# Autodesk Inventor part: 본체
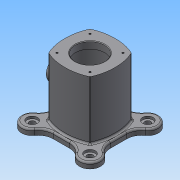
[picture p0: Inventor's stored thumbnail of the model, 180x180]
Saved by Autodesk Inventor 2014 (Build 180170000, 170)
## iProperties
Created: 2016-05
Part Number: 본체
Material: 일반
Document SubType Name: Modeling
Designer: NET
Density: 1 g/cm^3
Appearance: 기본값
Author: NET
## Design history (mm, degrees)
sketch "스케치5"
  geometry: L1 (0, 43)-(0, -43); L2 (-43, 0)-(43, 0); L3 (0, 0)-(35.355, 35.355); L4 (0, 0)-(-35.355, 35.355); L5 (0, 0)-(-35.355, -35.355); L6 (0, 0)-(35.355, -35.355); 4 further points; 4 other entities
  constraints: 12 end point, 2 coincident, 2 horizontal, 2 horizontal alignment, 2 midpoint, 2 vertical alignment, 18 other
  dimensions: "d44" = 50 distance of L3.end L3.start; "d46" = 50 distance of L4.end L3.start; "d47" = 50 distance of L5.end L3.start; "d48" = 45 deg angle of L2 L3; "d49" = 45 deg angle of L1 L4; "d50" = 45 deg angle of L1 L5; "d51" = 50 distance of L6.end L3.start; "d52" = 45 deg angle of L2 L6; "d53" = 86 distance of L1.end L1.start; "d54" = 86 distance of L2.start L2.end
extrude "돌출3" new body sketch "스케치5" distance "d55" = 110; taper "d56" = 0 deg
fillet "모깎기3" dims "d57" = 3
sketch "스케치6"
  geometry: L1 (110, -34.353)-(110, 34.353) reference; L2 (0, -34.353)-(0, 34.353) reference; L3 (110, 0)-(0, 0); L4 (110, -25)-(98, -25); L5 (98, -25)-(98, 0); L6 (98, -35)-(12, -35); L7 (12, -35)-(12, 0); L8 (0, -25)-(12, -25); L9 (12, -25)-(12, 0); L10 (98, -35)-(98, -25)
  constraints: 16 end point, 6 perpendicular, 5 point on line, 2 parallel, 1 midpoint
  dimensions: "d58" = 70 diameter of L6 L3; "d59" = 50 diameter of L4 L3; "d60" = 50 diameter of L8 L3; "d61" = 12 distance between parallel lines of L1 L5; "d62" = 12 distance between parallel lines of L2 L7
revolve "회전1" sketch "스케치6" stored, may be unused: angle "d63" = 90 deg
sketch "스케치7"
  geometry: L1 (-49, 49)-(49, 49); L2 (49, 49)-(49, -49); L3 (49, -49)-(-49, -49); L4 (-49, -49)-(-49, 49); L5 (0, 0)-(-49.497, -49.497); L6 (0, 0)-(0, -70); A1 r 18 centre (-49.497, -49.497) between (-34.706, -59.754) and (-59.754, -34.706); A2 r 25 centre (-14.162, -74) between (-14.162, -49) and (-34.706, -59.754); A3 r 25 centre (-74, -14.162) between (-59.754, -34.706) and (-49, -14.162); 3 further points
  constraints: 12 end point, 6 point on circle, 4 tangent, 3 centre point, 3 parallel, 2 coincident, 2 midpoint, 2 point on line, 1 horizontal, 1 horizontal alignment, 1 perpendicular, 1 vertical alignment
  dimensions: "d64" = 98 distance of L1.start L1.end; "d65" = 98 distance of L3.end L1.start; "d67" = 45 deg angle of L6 L5; "d68" = 18 radius of A1; "d69" = 25 radius of A2; "d70" = 25 radius of A3
extrude "돌출4" join sketch "스케치7" distance "d71" = 10; taper "d72" = 0 deg
sketch "스케치8" dims "d73" = 70
  geometry: L1 (49, -49)-(49, 14.162) reference; L2 (14.162, 49)-(-49, 49) reference; L3 (-49, 49)-(-49, -49) reference; L4 (-49, -49)-(49, -49) reference; L5 (0, 0)-(-49.497, 49.497); L6 (0, 0)-(0, 49); L7 (0, 0)-(-49.497, -49.497); L8 (0, 0)-(49.497, -49.497); C1 r 18 at (-49.497, 49.497); C2 r 18 at (-49.497, -49.497); C3 r 18 at (49.497, -49.497); A1 r 25 centre (-14.162, 74) between (-35.205, 60.503) and (-14.162, 49); A2 r 25 centre (-74, 14.162) between (-49, 14.162) and (-60.503, 35.205); A3 r 25 centre (-14.162, -74) between (-14.162, -49) and (-35.205, -60.503); A4 r 25 centre (-74, -14.162) between (-60.503, -35.205) and (-49, -14.162); A5 r 25 centre (14.162, -74) between (35.205, -60.503) and (14.162, -49); A6 r 25 centre (74, -14.162) between (49, -14.162) and (60.503, -35.205); 3 further points; 1 other entity
  constraints: 12 point on circle, 12 tangent, 9 centre point, 8 end point, 7 point on line, 4 coincident, 3 perpendicular, 12 other
  dimensions: "d75" = 45 deg angle of L6 L5; "d76" = 18 radius of C1; "d79" = 25 radius of A1; "d80" = 25 radius of A2; "d82" = 18 radius of C2; "d83" = 25 radius of A3; "d84" = 25 radius of A4; "d85" = 18 radius of C3; "d86" = 25 radius of A5; "d87" = 25 radius of A6
extrude "돌출5" join sketch "스케치8" distance "d88" = 10; taper "d89" = 0 deg
sketch "스케치9"
  geometry: L1 (49, -31.504)-(49, 14.162) reference; L2 (14.162, 49)-(-31.504, 49) reference; L3 (-49, 31.504)-(-49, -31.504) reference; L4 (-31.504, -49)-(31.504, -49) reference; A1 r 18 centre (-49.497, 49.497) between (-31.504, 49) and (-49, 31.504) reference; A2 r 18 centre (-49.497, -49.497) between (-49, -31.504) and (-31.504, -49) reference; A3 r 18 centre (49.497, -49.497) between (31.504, -49) and (49, -31.504) reference; A4 r 25 centre (-14.162, 74) between (-34.706, 59.754) and (-14.162, 49); A5 r 25 centre (-74, 14.162) between (-49, 14.162) and (-59.754, 34.706); A6 r 25 centre (-14.162, -74) between (-14.162, -49) and (-34.706, -59.754); A7 r 25 centre (14.162, -74) between (34.706, -59.754) and (14.162, -49); A8 r 25 centre (-74, -14.162) between (-59.754, -34.706) and (-49, -14.162); A9 r 25 centre (74, -14.162) between (49, -14.162) and (59.754, -34.706)
  constraints: 18 point on circle, 12 tangent, 6 centre point, 6 point on line
  dimensions: "d90" = 25 radius of A4; "d91" = 25 radius of A5; "d92" = 25 radius of A6; "d93" = 25 radius of A7; "d94" = 25 radius of A8; "d95" = 25 radius of A9
extrude "돌출6" join sketch "스케치9" distance "d96" = 10; taper "d97" = 0 deg
sketch "스케치10"
  geometry: C1 r 9 at (-49.497, 49.497); C2 r 9 at (49.497, 49.497); C3 r 9 at (49.497, -49.497); C4 r 9 at (-49.497, -49.497); A1 r 18 centre (49.497, 49.497) between (59.754, 34.706) and (34.706, 59.754) reference; A2 r 18 centre (-49.497, 49.497) between (-34.706, 59.754) and (-59.754, 34.706) reference; A3 r 18 centre (-49.497, -49.497) between (-59.754, -34.706) and (-34.706, -59.754) reference; A4 r 18 centre (49.497, -49.497) between (34.706, -59.754) and (59.754, -34.706) reference
  constraints: 4 centre point, 4 coincident
  dimensions: "d98" = 18 diameter of C1; "d99" = 18 diameter of C2; "d100" = 18 diameter of C3; "d101" = 18 diameter of C4
extrude "돌출7" cut sketch "스케치10" distance "d102" = 4; taper "d103" = 0 deg
sketch "스케치11"
  geometry: C1 r 9 at (0, 0) reference; C2 r 9 at (0, -98.995) reference; C3 r 9 at (98.995, -98.995) reference; C4 r 9 at (98.995, 0) reference; C5 r 5 at (0, -98.995); C6 r 5 at (98.995, -98.995); C7 r 5 at (98.995, 0); C8 r 5 at (0, 0); 1 further point
  constraints: 4 centre point, 4 coincident
  dimensions: "d104" = 10 diameter of C5; "d105" = 10 diameter of C6; "d106" = 10 diameter of C7; "d107" = 10 diameter of C8
extrude "돌출8" cut sketch "스케치11" stored distance "d108" = 4; taper "d109" = 0 deg
sketch "스케치12"
  geometry: L1 (0, 0)-(-28.284, 28.284); L2 (0, 0)-(0, 40); A1 r 40 centre (0, 0) between (-28.284, 28.284) and (0, 40); 3 further points; 1 other entity
  constraints: 4 end point, 2 point on circle, 1 centre point, 1 coincident, 1 vertical, 1 other
  dimensions: "d111" = 80 diameter of A1; "d112" = 45 deg angle of L2 L1
hole "구멍1" sketch "스케치12" at (-28.284, 28.284) diameter "d113" = 3.242; stored, may be unused: countersink angle "d117" = 90 deg, drill point angle "d119" = 118 deg; dims "d114" = 7, "d115" = 4, "d116" = 2, "d118" = 10
sketch "스케치13"
  geometry: C1 r 25 at (0, 0); 1 further point
  constraints: 1 centre point, 1 coincident
  dimensions: "d123" = 50 diameter of C1
extrude "돌출9" cut sketch "스케치13" distance "d124" = 50; taper "d125" = 0 deg
sketch "스케치14"
  geometry: L1 (-14.162, 49)-(14.162, 49) reference; L2 (0, 0)-(0, 40); L3 (0, 0)-(28.284, 28.284); C1 r 25 at (0, 0) reference; A1 r 40 centre (0, 0) between (0, 40) and (28.284, 28.284)
  constraints: 4 end point, 2 point on circle, 1 centre point, 1 coincident, 1 perpendicular
  dimensions: "d127" = 80 diameter of A1; "d128" = 45 deg angle of L2 L3
hole "구멍2" sketch "스케치14" at (28.284, 28.284) diameter "d129" = 3.242; stored, may be unused: countersink angle "d133" = 90 deg, drill point angle "d135" = 118 deg; dims "d130" = 7, "d131" = 4, "d132" = 2, "d134" = 10
node "작업 평면1"
sketch "스케치17"
  geometry: L1 (0, 0)-(49, 0); L2 (49, 0)-(61, 0); C1 r 20 at (61, 0)
  constraints: 4 end point, 1 centre point, 1 coincident, 1 collinear, 1 horizontal
  dimensions: "d146" = 49 distance of L1.start L1.end; "d147" = 12 distance of L1.end L2.end; "d148" = 40 diameter of C1
extrude "돌출11" join sketch "스케치17" stored distance "d149" = 50; taper "d150" = 10 deg
sketch "스케치19"
  geometry: C1 r 20 at (0, 0) reference; C2 r 15 at (0, 0); 1 further point
  constraints: 1 centre point, 1 coincident
  dimensions: "d151" = 30 diameter of C2
extrude "돌출12" cut sketch "스케치19" distance "d152" = 8; taper "d153" = 0 deg
sketch "스케치20"
  geometry: C1 r 15 at (0, 0) reference; C2 r 12.5 at (0, 0); 1 further point
  constraints: 1 centre point, 1 coincident
  dimensions: "d154" = 25 diameter of C2
extrude "돌출13" cut sketch "스케치20" distance "d155" = 33; taper "d156" = 0 deg
node "작업 평면2"
sketch "스케치21"
  geometry: L1 (10, 34.353)-(10, -34.353) reference; L2 (110, -34.353)-(10, -34.353) reference; L3 (110, 34.353)-(110, -34.353) reference; L4 (10, 34.353)-(110, 34.353) reference; L5 (10, 35.826)-(10, 35.826) reference; L6 (110, 35.826)-(10, 35.826) reference; L7 (110, 35.826)-(110, 35.826) reference; L8 (10, 35.826)-(110, 35.826) reference; L9 (110, 35.826)-(110, 43) reference; 3 further points
  constraints: 2 other
  dimensions: "d158" = 29 vertical distance of point (0, 0) point (61, 29); "d159" = 49 distance from line of L3 point (61, 29)
  node "투영된 루프3"
  node "투영된 루프4"
extrude "돌출14" join sketch "스케치21" distance "d162" = 0.5; taper "d163" = 0 deg
extrude "돌출15" join sketch "스케치21" distance "d164" = 0.5; taper "d165" = 0 deg
fillet "모깎기4" dims "d166" = 3
chamfer "모따기1" distance "d167" = 1; stored, may be unused: second distance "d168" = 2, angle "d169" = 45 deg
chamfer "모따기2" distance "d170" = 1; stored, may be unused: second distance "d171" = 2, angle "d172" = 45 deg
fillet "모깎기5" dims "d173" = 3
node "솔리드3"
pattern_circular "원형 패턴1" dims angle "d121" = 360 deg
pattern_circular "원형 패턴2" dims angle "d137" = 360 deg
node "투영된 루프1"
node "투영된 루프2"
other parameters: "d139" = 55, "d157" = 43
